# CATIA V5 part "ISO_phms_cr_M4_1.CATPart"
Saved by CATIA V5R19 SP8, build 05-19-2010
Part number: ISO_phms_cr_M4
Revision: ANY
Definition: UNKNOWN
Nomenclature: 5
Source: Unknown
Bounding box of the stored display mesh (mm): x -4.008 to 3.951, y -40 to 3.059, z -4.011 to 0.692
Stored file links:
  D:\Documents\1_Travail\2- 2I2D\1 - Cours et TD\2- TD\3-TD Assemblage\Pompe AirMan\ISO_phms_cr_M4_1.CATPart
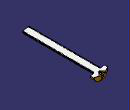
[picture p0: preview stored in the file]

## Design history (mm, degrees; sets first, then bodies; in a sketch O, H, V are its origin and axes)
Body1 "Enlèv. mat.-Extru.2" (main body)
  Solid1: solid without history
